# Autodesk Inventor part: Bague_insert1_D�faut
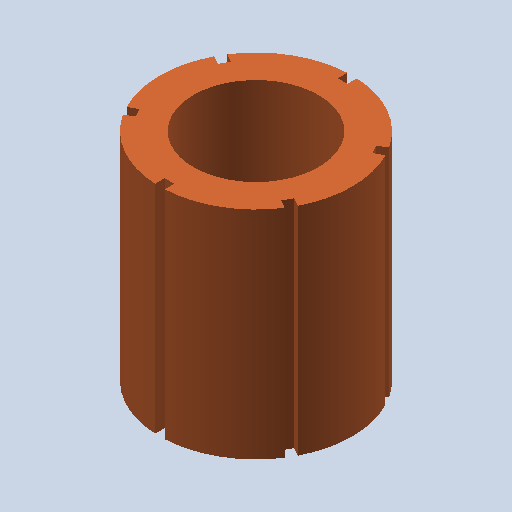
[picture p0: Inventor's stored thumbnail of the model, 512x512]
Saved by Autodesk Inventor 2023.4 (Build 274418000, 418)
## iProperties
Created: 2011-01
Part Number: Bague_insert1_D�faut
Document SubType Name: Modeling
Designer: eric
Density: 1 g/cm^3
Mass: 31.5814 g
Surface Area: 118.004 cm^2
Volume: 31.5814 cm^3
Material: Générique
Appearance: 255,128,64_1
Author: eric
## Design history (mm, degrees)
feature "Base1"
node "Corps solides"
node "Corps surfaciques"
node "Solide1"
